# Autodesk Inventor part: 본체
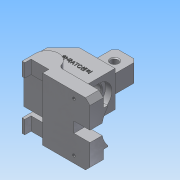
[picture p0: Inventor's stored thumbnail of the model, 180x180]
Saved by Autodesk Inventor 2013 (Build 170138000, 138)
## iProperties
Created: 2016-11
Part Number: 본체
Material: 알루미늄 6061
Document SubType Name: Modeling
Designer: Administrator
Density: 2.71 g/cm^3
Mass: 448.163 g
Surface Area: 314.41 cm^2
Volume: 165.374 cm^3
Author: Administrator
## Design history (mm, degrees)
sketch "스케치3"
  geometry: L1 (-9, 18)-(-27, 0); L2 (-27, 0)-(-27, -30); L3 (-27, -30)-(10, -30); L4 (10, -30)-(10, -42); L5 (10, -42)-(63, -42); L6 (63, -42)-(63, -22); L7 (63, -22)-(31, -22); L8 (31, -22)-(31, 18); L9 (31, 18)-(-9, 18); 1 further point
  constraints: 18 end point, 7 perpendicular, 1 vertical
  dimensions: "d4" = 48 distance between parallel lines of L9 L3; "d7" = 30 distance from line of point (0, 0) L3; "d8" = 45 deg angle of L9 L1; "d9" = 18 distance from line of L1.start L2; "d10" = 63 distance from line of point (0, 0) L6; "d11" = 20 distance of L5.end L6.end; "d12" = 90 distance between parallel lines of L2 L6; "d13" = 58 distance between parallel lines of L8 L2; "d14" = 10 distance from line of point (0, 0) L4; "d15" = 60 distance between parallel lines of L5 L9
extrude "돌출1" new body sketch "스케치3" stored distance "d16" = 40; taper "d17" = 0 deg
sketch "스케치4"
  geometry: L1 (1, 48)-(26, 48); L2 (26, 48)-(26, 18); L3 (26, 18)-(1, 18); L4 (1, 18)-(1, 48); L5 (-9, 18)-(31, 18) reference; L6 (31, 18)-(31, -22) reference; L7 (63, -42)-(10, -42) reference; 2 further points
  constraints: 8 end point, 2 parallel, 1 horizontal, 1 midpoint, 1 perpendicular, 1 point on line
  dimensions: "d18" = 25 distance of L1.start L1.end; "d20" = 5 distance between parallel lines of L6 L2; "d21" = 90 distance between parallel lines of L7 L1
extrude "돌출2" join sketch "스케치4" stored distance "d22" = 20; taper "d23" = 0 deg
sketch "스케치6"
  geometry: L1 (1, 48)-(1, 18) reference; C1 r 4 at (13.5, 35); 1 further point
  constraints: 1 centre point
  dimensions: "d25" = 8 diameter of C1; "d26" = 35 vertical distance of C1.centre point (0, 0); "d27" = 12.5 distance from line of L1 C1.centre
extrude "돌출3" cut sketch "스케치6" stored distance "d28" = 20; taper "d29" = 0 deg
chamfer "모따기1" distance "d30" = 4; stored, may be unused: second distance "d31" = 2, angle "d32" = 45 deg
sketch "스케치7"
  geometry: 2 further points
  constraints: 1 coincident
hole "구멍1" sketch "스케치7" at (20, 22) diameter "d33" = 20; stored, may be unused: countersink angle "d37" = 90 deg, drill point angle "d39" = 0 deg; dims "d34" = 6, "d35" = 29, "d36" = 7, "d38" = 8
chamfer "모따기2" distance "d40" = 1; stored, may be unused: second distance "d41" = 2, angle "d42" = 45 deg
node "작업 평면1"
sketch "스케치9"
  geometry: L1 (40, 20)-(0, 20) reference; A1 r 29 centre (20, 42) between (1.106, 20) and (38.894, 20); 1 further point
  constraints: 2 point on circle, 2 point on line, 1 centre point, 1 coincident
  dimensions: "d44" = 29 radius of A1
extrude "돌출4" cut sketch "스케치9" stored distance "d45" = 20; taper "d46" = 0 deg
sketch "스케치10"
  geometry: L1 (40, 0)-(0, 0) reference; L2 (14, 20)-(26, 20); L3 (26, 20)-(26, 0); L4 (26, 0)-(14, 0); L5 (14, 0)-(14, 20); L6 (1.106, 20)-(38.894, 20) reference; A1 r 29 centre (20, 42) between (1.106, 20) and (38.894, 20) reference; 3 further points
  constraints: 8 end point, 4 midpoint, 2 parallel, 1 coincident, 1 horizontal, 1 perpendicular, 1 vertical alignment
  dimensions: "d47" = 12 distance of L2.start L2.end
extrude "돌출5" cut sketch "스케치10" distance "d49" = 18; taper "d50" = 0 deg
sketch "스케치11"
  geometry: L1 (10, -30)-(10, -42) reference; L2 (10, -42)-(63, -42) reference; L3 (63, -42)-(63, -22) reference; L4 (-10, -35)-(-10, -42); L5 (-10, -42)-(-13, -42); L6 (-13, -42)-(-13, -27); L7 (10, -42)-(63, -42); L8 (63, -42)-(63, -27); L9 (63, -27)-(13, -27); L10 (10, -42)-(10, -35); L11 (10, -35)-(-10, -35); A1 r 13 centre (0, -27) between (13, -27) and (-13, -27); 3 further points
  constraints: 16 end point, 2 horizontal alignment, 2 midpoint, 2 perpendicular, 2 point on circle, 2 point on line, 1 centre point, 1 collinear, 1 horizontal, 1 parallel, 1 tangent, 1 vertical, 1 vertical alignment
  dimensions: "d51" = 3 distance of L4.end L5.end; "d52" = 15 distance of L2.end L8.end; "d79" = 7 distance between parallel lines of L2 L11; "d80" = 20 distance of L10.end L4.start
extrude "돌출6" join sketch "스케치11" distance "d56" = 15; taper "d57" = 0 deg
fillet "모깎기1" dims "d58" = 5
chamfer "모따기3" distance "d59" = 5; stored, may be unused: second distance "d60" = 2, angle "d61" = 45 deg
sketch "스케치12"
  geometry: L1 (45.708, 0)-(45.708, -10) reference; 2 further points
  dimensions: "d62" = 27.5 vertical distance of point (-17.292, 20) point (27.708, -7.5); "d63" = 18 distance from line of L1 point (27.708, -7.5)
hole "구멍2" sketch "스케치12" at (27.708, -7.5) diameter "d64" = 3.242; stored, may be unused: countersink angle "d68" = 90 deg, drill point angle "d70" = 0 deg; dims "d65" = 15, "d66" = 29, "d67" = 7, "d69" = 8
chamfer "모따기4" distance "d71" = 1; stored, may be unused: second distance "d72" = 2, angle "d73" = 45 deg
fillet "모깎기2" dims "d74" = 3
sketch "스케치13"
  geometry: L1 (31, -19)-(31, 18) reference; L2 (31, 18)-(-9, 18) reference; 2 further points
  constraints: 1 other
  dimensions: "d75" = 25 distance from line of L1 point (6, 0); "d76" = 18 distance from line of L2 point (6, 0)
feature "엠보싱1" sketch "스케치13" dims "d4" = 48, "d7" = 30, "d8" = 45 deg, "d9" = 18, "d10" = 63, "d11" = 20, "d12" = 90, "d13" = 58, "d14" = 10, "d15" = 60, "d21" = 90, "d77" = 0.5, "d78" = 0
node "솔리드1"
mirror "대칭1"
mirror "대칭2"
other parameters: "d43" = -18, "d53" = 26
